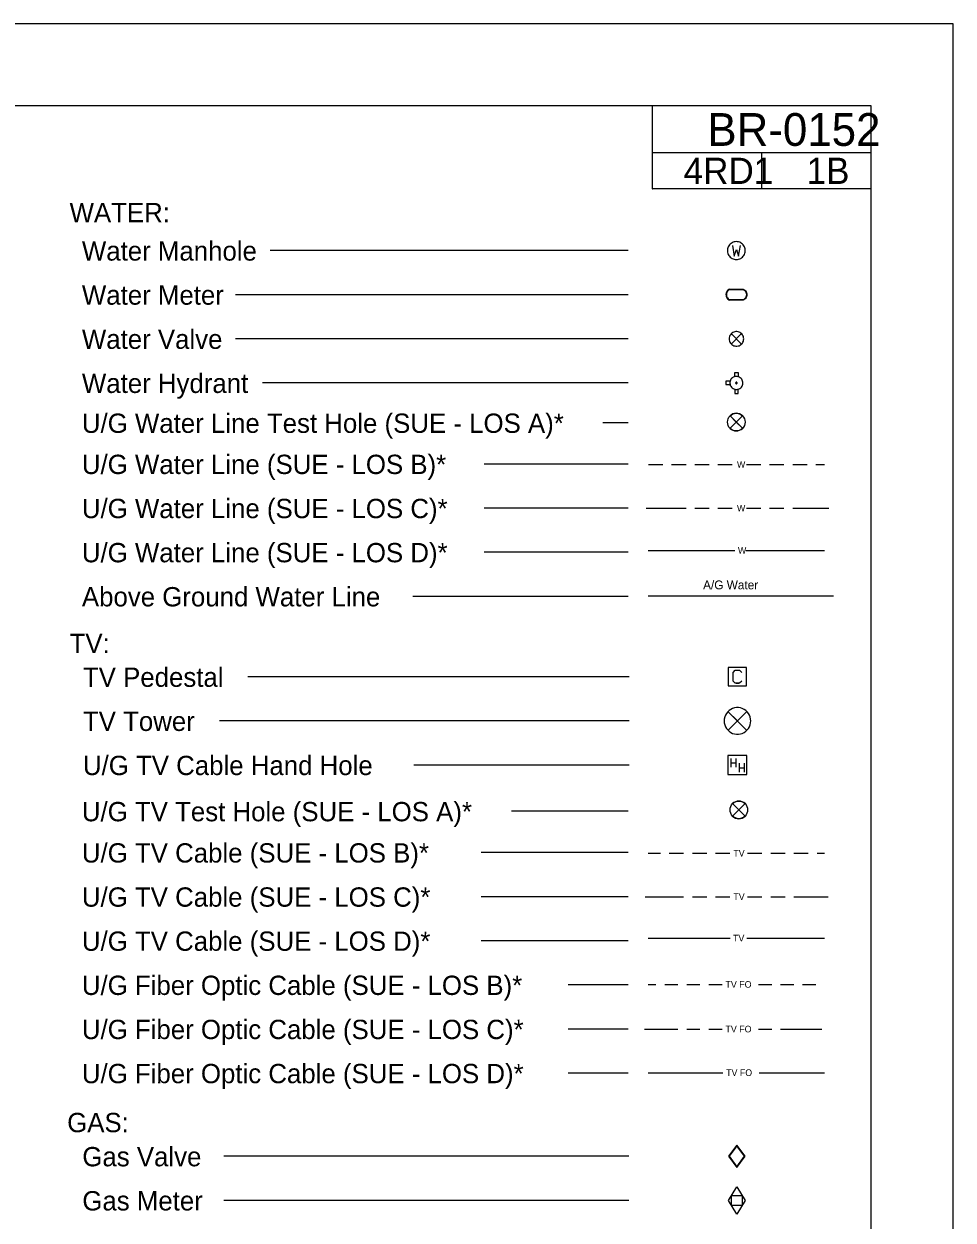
# Model space of a CAD drawing. Extents: x 1552903 to 1553044, y 811448 to 811540.
# Drawn here: x 1553008.81 to 1553044.23, y 811494.51 to 811540.09 of the extents above; entities that cross this region are included whole.
import ezdxf

# ---------------------------------------------------------------- set-up
doc = ezdxf.new("R2010")
doc.units = 0
for name, color, linetype in [('Exist DTM Breakline', 7, 'Continuous'), ('Exist Structure Major Bridge WW', 7, 'Continuous'), ('Exist Utilities TV Test Hole SUE LOS A CELL', 7, 'Continuous'), ('Exist Utilities Water Test Hole SUE LOS A CELL', 7, 'Continuous'), ('Sheet_Plan_CELL', 7, 'Continuous'), ('Sheet_Title_Block_Text', 7, 'Continuous'), ('z - Construction', 7, 'Continuous')]:
    doc.layers.add(name, color=color, linetype=linetype)

msp = doc.modelspace()

# ---------------------------------------------------------------- linework, layer by layer
at = {"layer": 'Exist DTM Breakline'}
for p, q in [((1553031.849, 811531.45), (1553018.196, 811531.45)), ((1553031.849, 811529.768), (1553016.88, 811529.768)), ((1553035.713, 811529.984), (1553036.23, 811529.984)), ((1553035.713, 811529.968), (1553036.23, 811529.968)), ((1553036.226, 811529.573), (1553035.713, 811529.573)), ((1553036.226, 811529.556), (1553035.713, 811529.556)), ((1553031.849, 811528.087), (1553016.88, 811528.087)), ((1553031.849, 811526.405), (1553017.91, 811526.405)), ((1553031.849, 811524.884), (1553030.878, 811524.884)), ((1553031.849, 811523.317), (1553026.352, 811523.317)), ((1553032.62, 811523.299), (1553033.167, 811523.299)), ((1553033.503, 811523.299), (1553034.05, 811523.299)), ((1553034.386, 811523.299), (1553034.932, 811523.299)), ((1553035.269, 811523.299), (1553035.815, 811523.299)), ((1553036.353, 811523.299), (1553036.9, 811523.299)), ((1553037.236, 811523.299), (1553037.783, 811523.299)), ((1553038.119, 811523.299), (1553038.665, 811523.299)), ((1553039.002, 811523.299), (1553039.333, 811523.299)), ((1553031.849, 811521.635), (1553026.352, 811521.635)), ((1553032.525, 811521.635), (1553034.05, 811521.635)), ((1553034.386, 811521.635), (1553034.932, 811521.635)), ((1553035.269, 811521.635), (1553035.815, 811521.635)), ((1553036.353, 811521.635), (1553036.9, 811521.635)), ((1553037.236, 811521.635), (1553037.783, 811521.635)), ((1553038.119, 811521.635), (1553039.49, 811521.635)), ((1553031.849, 811519.954), (1553026.352, 811519.954)), ((1553032.607, 811520.027), (1553035.911, 811520.027)), ((1553036.331, 811520.027), (1553039.333, 811520.027)), ((1553031.849, 811518.272), (1553023.633, 811518.272)), ((1553032.607, 811518.29), (1553039.67, 811518.29)), ((1553031.889, 811515.208), (1553017.351, 811515.208)), ((1553035.957, 811514.961), (1553036.066, 811514.961)), ((1553031.889, 811513.526), (1553016.264, 811513.526)), ((1553031.889, 811511.845), (1553023.674, 811511.845)), ((1553035.752, 811512.099), (1553035.752, 811511.76)), ((1553035.752, 811511.927), (1553035.946, 811511.927)), ((1553035.946, 811512.099), (1553035.946, 811511.76)), ((1553036.076, 811511.915), (1553036.076, 811511.576)), ((1553036.269, 811511.915), (1553036.269, 811511.576)), ((1553036.076, 811511.742), (1553036.269, 811511.742)), ((1553031.849, 811510.085), (1553027.404, 811510.085)), ((1553031.849, 811508.511), (1553026.242, 811508.511)), ((1553032.607, 811508.484), (1553033.075, 811508.484)), ((1553033.412, 811508.484), (1553033.958, 811508.484)), ((1553034.294, 811508.484), (1553034.841, 811508.484)), ((1553035.177, 811508.484), (1553035.724, 811508.484)), ((1553036.396, 811508.484), (1553036.943, 811508.484)), ((1553037.279, 811508.484), (1553037.826, 811508.484)), ((1553038.162, 811508.484), (1553038.709, 811508.484)), ((1553039.045, 811508.484), (1553039.333, 811508.484)), ((1553031.849, 811506.83), (1553026.242, 811506.83)), ((1553032.49, 811506.83), (1553033.958, 811506.83)), ((1553034.294, 811506.83), (1553034.841, 811506.83)), ((1553035.177, 811506.83), (1553035.724, 811506.83)), ((1553036.396, 811506.83), (1553036.943, 811506.83)), ((1553037.279, 811506.83), (1553037.826, 811506.83)), ((1553038.162, 811506.83), (1553039.474, 811506.83)), ((1553031.849, 811505.148), (1553026.242, 811505.148)), ((1553032.607, 811505.25), (1553035.732, 811505.25)), ((1553036.363, 811505.25), (1553039.333, 811505.25)), ((1553031.849, 811503.467), (1553029.559, 811503.467)), ((1553032.607, 811503.487), (1553032.901, 811503.487)), ((1553033.237, 811503.487), (1553033.742, 811503.487)), ((1553034.078, 811503.487), (1553034.582, 811503.487)), ((1553034.919, 811503.487), (1553035.423, 811503.487)), ((1553036.811, 811503.487), (1553037.315, 811503.487)), ((1553037.651, 811503.487), (1553038.156, 811503.487)), ((1553038.492, 811503.487), (1553038.997, 811503.487)), ((1553031.849, 811501.785), (1553029.559, 811501.785)), ((1553032.469, 811501.785), (1553033.742, 811501.785)), ((1553034.078, 811501.785), (1553034.582, 811501.785)), ((1553034.919, 811501.785), (1553035.423, 811501.785)), ((1553036.811, 811501.785), (1553037.315, 811501.785)), ((1553037.651, 811501.785), (1553039.226, 811501.785)), ((1553031.849, 811500.103), (1553029.559, 811500.103)), ((1553032.607, 811500.123), (1553035.447, 811500.123)), ((1553036.835, 811500.123), (1553039.333, 811500.123)), ((1553035.987, 811497.333), (1553035.691, 811496.936)), ((1553036.282, 811496.936), (1553035.987, 811497.333)), ((1553031.866, 811496.936), (1553016.439, 811496.936)), ((1553035.691, 811496.936), (1553035.987, 811496.54)), ((1553035.987, 811496.54), (1553036.282, 811496.936)), ((1553031.866, 811495.255), (1553016.439, 811495.255))]:
    msp.add_line(p, q, dxfattribs=at)
for points in [[(1553035.97, 811531.791), (1553035.926, 811531.789), (1553035.885, 811531.78), (1553035.844, 811531.767), (1553035.806, 811531.748), (1553035.77, 811531.726), (1553035.738, 811531.698), (1553035.707, 811531.666), (1553035.683, 811531.633), (1553035.661, 811531.595), (1553035.647, 811531.554), (1553035.637, 811531.513), (1553035.631, 811531.472), (1553035.631, 811531.428), (1553035.637, 811531.387), (1553035.647, 811531.343), (1553035.661, 811531.305), (1553035.683, 811531.267), (1553035.707, 811531.234), (1553035.738, 811531.201), (1553035.77, 811531.174), (1553035.806, 811531.152), (1553035.844, 811531.133), (1553035.885, 811531.119), (1553035.929, 811531.111), (1553035.97, 811531.109), (1553036.013, 811531.111), (1553036.054, 811531.119), (1553036.095, 811531.133), (1553036.134, 811531.152), (1553036.169, 811531.174), (1553036.202, 811531.201), (1553036.232, 811531.234), (1553036.257, 811531.267), (1553036.278, 811531.305), (1553036.292, 811531.346), (1553036.303, 811531.387), (1553036.308, 811531.428), (1553036.308, 811531.472), (1553036.303, 811531.513), (1553036.292, 811531.556), (1553036.278, 811531.595), (1553036.257, 811531.633), (1553036.232, 811531.666), (1553036.202, 811531.698), (1553036.169, 811531.726), (1553036.134, 811531.748), (1553036.095, 811531.767), (1553036.054, 811531.78), (1553036.011, 811531.789), (1553035.97, 811531.791)], [(1553035.817, 811531.638), (1553035.888, 811531.24), (1553035.97, 811531.491), (1553036.054, 811531.24), (1553036.125, 811531.638)], [(1553035.713, 811529.984), (1553035.679, 811529.968), (1553035.649, 811529.944), (1553035.622, 811529.914), (1553035.602, 811529.883), (1553035.585, 811529.846), (1553035.575, 811529.809), (1553035.571, 811529.772), (1553035.575, 811529.731), (1553035.585, 811529.694), (1553035.602, 811529.66), (1553035.622, 811529.626), (1553035.649, 811529.599), (1553035.679, 811529.576), (1553035.713, 811529.556)], [(1553035.72, 811529.971), (1553035.686, 811529.951), (1553035.656, 811529.927), (1553035.629, 811529.897), (1553035.608, 811529.866), (1553035.595, 811529.829), (1553035.588, 811529.789), (1553035.588, 811529.751), (1553035.595, 811529.714), (1553035.608, 811529.677), (1553035.629, 811529.643), (1553035.656, 811529.613), (1553035.686, 811529.589), (1553035.72, 811529.573)], [(1553036.22, 811529.971), (1553036.257, 811529.954), (1553036.287, 811529.927), (1553036.311, 811529.9), (1553036.331, 811529.866), (1553036.345, 811529.829), (1553036.351, 811529.789), (1553036.351, 811529.751), (1553036.345, 811529.711), (1553036.331, 811529.677), (1553036.311, 811529.643), (1553036.284, 811529.613), (1553036.253, 811529.589), (1553036.22, 811529.569)], [(1553036.226, 811529.984), (1553036.26, 811529.968), (1553036.29, 811529.944), (1553036.318, 811529.914), (1553036.338, 811529.883), (1553036.355, 811529.846), (1553036.365, 811529.809), (1553036.368, 811529.772), (1553036.365, 811529.731), (1553036.355, 811529.694), (1553036.338, 811529.66), (1553036.318, 811529.626), (1553036.29, 811529.599), (1553036.26, 811529.576), (1553036.226, 811529.556)], [(1553036.249, 811528.087), (1553036.246, 811528.127), (1553036.237, 811528.171), (1553036.221, 811528.208), (1553036.199, 811528.245), (1553036.174, 811528.276), (1553036.143, 811528.304), (1553036.109, 811528.329), (1553036.072, 811528.347), (1553036.032, 811528.36), (1553035.991, 811528.366), (1553035.948, 811528.366), (1553035.908, 811528.36), (1553035.867, 811528.347), (1553035.83, 811528.329), (1553035.796, 811528.304), (1553035.765, 811528.276), (1553035.74, 811528.245), (1553035.718, 811528.208), (1553035.703, 811528.171), (1553035.694, 811528.127), (1553035.69, 811528.087), (1553035.694, 811528.046), (1553035.703, 811528.003), (1553035.718, 811527.966), (1553035.74, 811527.928), (1553035.765, 811527.897), (1553035.796, 811527.87), (1553035.83, 811527.845), (1553035.867, 811527.826), (1553035.908, 811527.814), (1553035.948, 811527.808), (1553035.991, 811527.808), (1553036.032, 811527.814), (1553036.072, 811527.826), (1553036.109, 811527.845), (1553036.143, 811527.87), (1553036.174, 811527.897), (1553036.199, 811527.928), (1553036.221, 811527.966), (1553036.237, 811528.003), (1553036.246, 811528.046), (1553036.249, 811528.087)], [(1553036.168, 811527.888), (1553035.771, 811528.285), (1553035.97, 811528.087), (1553035.771, 811527.888), (1553036.168, 811528.285)], [(1553035.731, 811526.47), (1553035.57, 811526.47), (1553035.57, 811526.341), (1553035.731, 811526.341)], [(1553035.967, 811526.654), (1553035.928, 811526.65), (1553035.889, 811526.641), (1553035.85, 811526.625), (1553035.818, 811526.602), (1553035.789, 811526.576), (1553035.763, 811526.544), (1553035.744, 811526.508), (1553035.731, 811526.47), (1553035.721, 811526.431), (1553035.721, 811526.392), (1553035.728, 811526.354), (1553035.737, 811526.315), (1553035.757, 811526.279), (1553035.779, 811526.247), (1553035.808, 811526.218), (1553035.841, 811526.192), (1553035.876, 811526.176), (1553035.915, 811526.163), (1553035.954, 811526.157), (1553035.992, 811526.157), (1553036.031, 811526.163), (1553036.07, 811526.179), (1553036.105, 811526.195), (1553036.138, 811526.221), (1553036.163, 811526.25), (1553036.186, 811526.283), (1553036.202, 811526.321), (1553036.215, 811526.36), (1553036.218, 811526.399), (1553036.215, 811526.438), (1553036.208, 811526.476), (1553036.192, 811526.515), (1553036.173, 811526.551), (1553036.147, 811526.58), (1553036.115, 811526.605), (1553036.083, 811526.628), (1553036.044, 811526.641), (1553036.005, 811526.65), (1553035.967, 811526.654)], [(1553035.908, 811526.647), (1553035.908, 811526.809), (1553036.037, 811526.809), (1553036.037, 811526.644)], [(1553035.97, 811526.434), (1553035.957, 811526.431), (1553035.947, 811526.421), (1553035.941, 811526.408), (1553035.944, 811526.396), (1553035.95, 811526.383), (1553035.963, 811526.376), (1553035.976, 811526.376), (1553035.989, 811526.383), (1553035.996, 811526.396), (1553035.999, 811526.408), (1553035.992, 811526.421), (1553035.983, 811526.431), (1553035.97, 811526.434)], [(1553035.908, 811526.163), (1553035.908, 811526.002), (1553036.037, 811526.002), (1553036.037, 811526.166)], [(1553035.66, 811514.858), (1553036.36, 811514.858), (1553036.36, 811515.558), (1553035.66, 811515.558), (1553035.66, 811514.858)], [(1553036.174, 811515.038), (1553036.091, 811514.961), (1553035.929, 811514.961), (1553035.851, 811515.038), (1553035.851, 811515.378), (1553035.929, 811515.455), (1553036.091, 811515.455), (1553036.174, 811515.378)], [(1553036.516, 811513.526), (1553036.511, 811513.6), (1553036.494, 811513.678), (1553036.466, 811513.746), (1553036.426, 811513.813), (1553036.381, 811513.87), (1553036.325, 811513.92), (1553036.263, 811513.965), (1553036.196, 811513.999), (1553036.122, 811514.022), (1553036.049, 811514.033), (1553035.97, 811514.033), (1553035.897, 811514.022), (1553035.824, 811513.999), (1553035.757, 811513.965), (1553035.695, 811513.92), (1553035.639, 811513.87), (1553035.594, 811513.813), (1553035.554, 811513.746), (1553035.526, 811513.678), (1553035.509, 811513.6), (1553035.504, 811513.526), (1553035.509, 811513.453), (1553035.526, 811513.374), (1553035.554, 811513.307), (1553035.594, 811513.239), (1553035.639, 811513.183), (1553035.695, 811513.132), (1553035.757, 811513.087), (1553035.824, 811513.054), (1553035.897, 811513.031), (1553035.97, 811513.02), (1553036.049, 811513.02), (1553036.122, 811513.031), (1553036.196, 811513.054), (1553036.263, 811513.087), (1553036.325, 811513.132), (1553036.381, 811513.183), (1553036.426, 811513.239), (1553036.466, 811513.307), (1553036.494, 811513.374), (1553036.511, 811513.453), (1553036.516, 811513.526)], [(1553036.37, 811513.166), (1553035.65, 811513.887), (1553036.01, 811513.526), (1553035.65, 811513.166), (1553036.37, 811513.887)], [(1553035.648, 811511.483), (1553036.372, 811511.483), (1553036.372, 811512.207), (1553035.648, 811512.207), (1553035.648, 811511.483)], [(1553035.987, 811497.367), (1553035.666, 811496.936), (1553035.987, 811496.506), (1553036.308, 811496.936), (1553035.987, 811497.367)], [(1553035.666, 811495.255), (1553035.987, 811495.774), (1553036.308, 811495.255), (1553035.987, 811494.736), (1553035.666, 811495.255)], [(1553035.789, 811495.449), (1553036.185, 811495.449), (1553036.185, 811495.056), (1553035.789, 811495.056), (1553035.789, 811495.449)]]:
    msp.add_lwpolyline(points, dxfattribs=at)
at = {"layer": 'Exist Structure Major Bridge WW'}
for p, q in [((1553041.105, 811536.962), (1552905.688, 811536.962)), ((1553032.771, 811533.802), (1553032.771, 811536.962)), ((1553041.103, 811451.545), (1553041.105, 811536.962)), ((1553041.105, 811533.802), (1553032.771, 811533.802))]:
    msp.add_line(p, q, dxfattribs=at)
msp.add_circle((1553032.771, 811533.802), 0.005, dxfattribs=at)
at = {"layer": 'Exist Utilities TV Test Hole SUE LOS A CELL'}
for points in [[(1553036.3, 811510.375), (1553035.825, 811509.9), (1553036.063, 811510.138), (1553035.825, 811510.375), (1553036.3, 811509.9)], [(1553035.825, 811510.375), (1553036.063, 811510.138), (1553036.3, 811510.375)], [(1553036.3, 811509.9), (1553036.063, 811510.138), (1553035.825, 811509.9)]]:
    msp.add_lwpolyline(points, dxfattribs=at)
msp.add_circle((1553036.063, 811510.138), 0.336, dxfattribs=at)
for start, end in [(45, 135), (225, 315)]:
    msp.add_arc((1553036.063, 811510.138), 0.336, start, end, dxfattribs=at)
at = {"layer": 'Exist Utilities Water Test Hole SUE LOS A CELL'}
for points in [[(1553036.204, 811525.152), (1553035.729, 811524.677), (1553035.967, 811524.914), (1553035.729, 811525.152), (1553036.204, 811524.677)], [(1553035.729, 811525.152), (1553035.967, 811524.914), (1553036.204, 811525.152)], [(1553036.204, 811524.677), (1553035.967, 811524.914), (1553035.729, 811524.677)]]:
    msp.add_lwpolyline(points, dxfattribs=at)
msp.add_circle((1553035.967, 811524.914), 0.336, dxfattribs=at)
for start, end in [(45, 135), (225, 315)]:
    msp.add_arc((1553035.967, 811524.914), 0.336, start, end, dxfattribs=at)
at = {"layer": 'Sheet_Plan_CELL'}
for p, q in [((1553041.105, 811535.177), (1553032.771, 811535.177)), ((1553036.938, 811533.802), (1553036.938, 811535.177))]:
    msp.add_line(p, q, dxfattribs=at)
at = {"layer": 'z - Construction'}
for p, q in [((1553044.23, 811540.087), (1552902.563, 811540.087)), ((1553044.23, 811448.42), (1553044.23, 811540.087))]:
    msp.add_line(p, q, dxfattribs=at)

# ---------------------------------------------------------------- texts
at = {"layer": 'Exist DTM Breakline'}
for s, height, p in [('WATER:', 0.7357, (1553010.554, 811532.529)), ('Water Manhole', 0.73569, (1553011.023, 811531.068)), ('Water Meter', 0.73569, (1553011.023, 811529.387)), ('Water Valve', 0.73569, (1553011.023, 811527.705)), ('Water Hydrant', 0.73569, (1553011.023, 811526.024)), ('U/G Water Line Test Hole (SUE - LOS A)*', 0.73569, (1553011.023, 811524.503)), ('U/G Water Line (SUE - LOS B)*', 0.73569, (1553011.023, 811522.935)), ('W', 0.252, (1553035.992, 811523.172)), ('U/G Water Line (SUE - LOS C)*', 0.73569, (1553011.023, 811521.254)), ('W', 0.252, (1553035.992, 811521.509)), ('U/G Water Line (SUE - LOS D)*', 0.73569, (1553011.023, 811519.572)), ('W', 0.252, (1553036.029, 811519.901)), ('A/G Water', 0.3363, (1553034.702, 811518.542)), ('Above Ground Water Line', 0.73569, (1553011.023, 811517.891)), ('TV:', 0.7357, (1553010.554, 811516.111)), ('TV Pedestal', 0.73569, (1553011.063, 811514.826)), ('TV Tower', 0.7357, (1553011.063, 811513.145)), ('U/G TV Cable Hand Hole', 0.73569, (1553011.063, 811511.463)), ('U/G TV Test Hole (SUE - LOS A)*', 0.73569, (1553011.023, 811509.703)), ('U/G TV Cable (SUE - LOS B)*', 0.73569, (1553011.023, 811508.13)), ('TV', 0.2522, (1553035.854, 811508.358)), ('U/G TV Cable (SUE - LOS C)*', 0.73569, (1553011.023, 811506.448)), ('TV', 0.2522, (1553035.854, 811506.704)), ('U/G TV Cable (SUE - LOS D)*', 0.73569, (1553011.023, 811504.767)), ('TV', 0.2522, (1553035.842, 811505.124)), ('U/G Fiber Optic Cable (SUE - LOS B)*', 0.73569, (1553011.023, 811503.085)), ('TV FO', 0.2522, (1553035.554, 811503.361)), ('U/G Fiber Optic Cable (SUE - LOS C)*', 0.73569, (1553011.023, 811501.403)), ('TV FO', 0.2522, (1553035.554, 811501.659)), ('U/G Fiber Optic Cable (SUE - LOS D)*', 0.73569, (1553011.023, 811499.722)), ('TV FO', 0.2522, (1553035.578, 811499.997)), ('GAS:', 0.7357, (1553010.462, 811497.855)), ('Gas Valve', 0.7357, (1553011.04, 811496.555)), ('Gas Meter', 0.7357, (1553011.04, 811494.873))]:
    msp.add_text(s, height=height, dxfattribs=at).set_placement(p)
at = {"layer": 'Sheet_Title_Block_Text'}
for s, height, p in [('BR-0152', 1.25, (1553034.864, 811535.439)), ('4RD1', 1, (1553033.958, 811533.989)), ('1B', 1, (1553038.644, 811533.989))]:
    msp.add_text(s, height=height, dxfattribs=at).set_placement(p)

doc.saveas('drawing.dxf')
